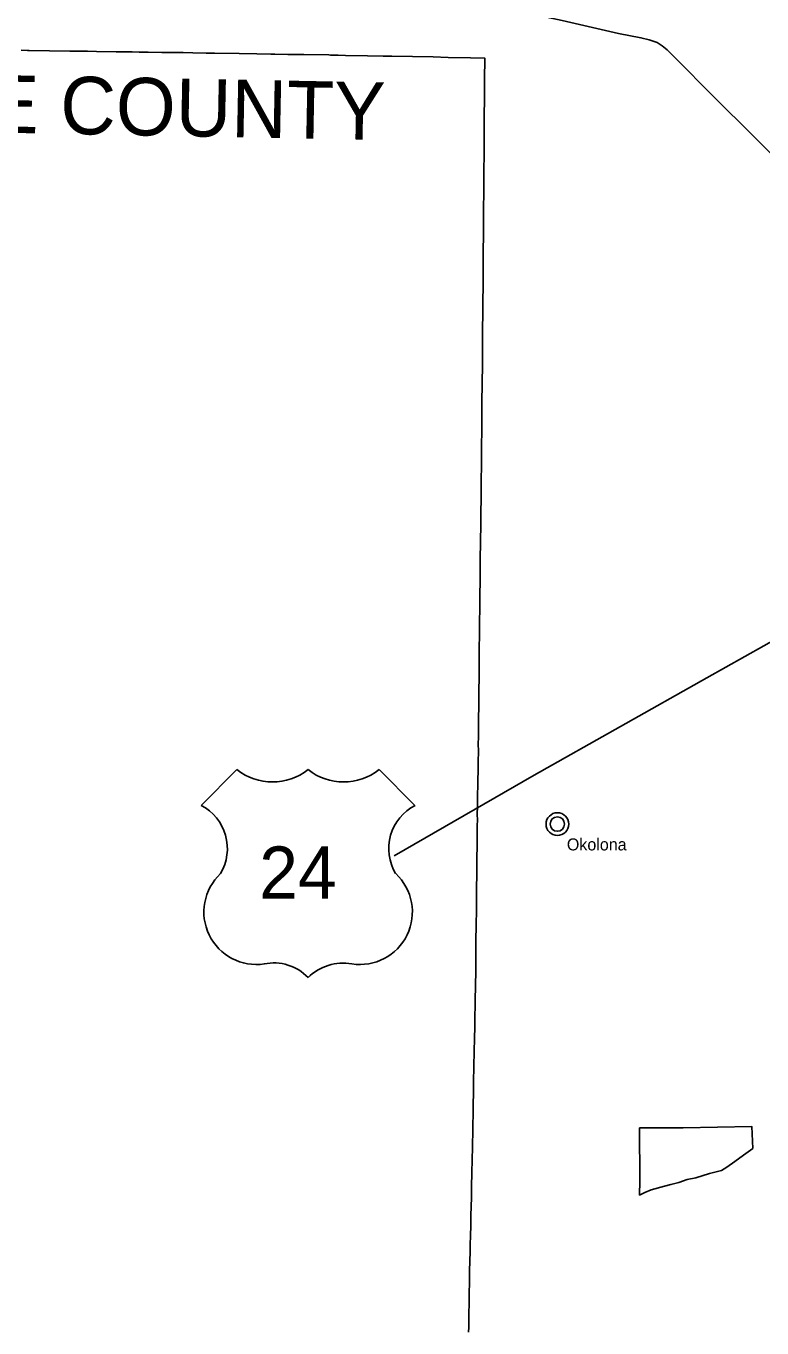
# Model space of a CAD drawing. Extents: x -62 to 810, y 0 to 440.
# Drawn here: x 166.9 to 239.8, y 199.3 to 328.2 of the extents above; entities that cross this region are included whole.
import ezdxf

# ---------------------------------------------------------------- set-up
doc = ezdxf.new("R2010")
doc.units = 0
for name, color, linetype in [('DV_X_Corp_Line', 7, 'Continuous'), ('GM_X_Adjacent_County_Text', 7, 'Continuous'), ('GM_X_Corporation_Text', 7, 'Continuous'), ('GM_X_County', 7, 'Continuous'), ('GM_X_State_Route', 7, 'Continuous'), ('PV_P_Text', 7, 'Continuous')]:
    doc.layers.add(name, color=color, linetype=linetype)

msp = doc.modelspace()

# ---------------------------------------------------------------- linework, layer by layer
at = {"layer": 'DV_X_Corp_Line'}
msp.add_lwpolyline([(227.72, 219.13), (232.04, 219.14), (238.83, 219.27), (238.92, 217.11), (238.02, 216.42), (237.15, 215.81), (236.36, 215.24), (235.84, 214.93), (234.64, 214.61), (233.27, 214.18), (232.41, 214.01), (231.6, 213.73), (230.81, 213.53), (230.18, 213.36), (228.86, 213), (228.24, 212.73), (227.71, 212.48), (227.73, 213.88)], close=True, dxfattribs=at)
for radius in [1.12, 0.71]:
    msp.add_circle((219.57, 249.22), radius, dxfattribs=at)
at = {"layer": 'GM_X_County'}
msp.add_lwpolyline([(166.45, 325.84), (167.1, 325.82), (167.25, 325.82), (171.27, 325.77), (172.55, 325.75), (173.04, 325.74), (173.92, 325.73), (175.87, 325.7), (177.45, 325.68), (178.15, 325.66), (178.52, 325.66), (179.03, 325.65), (180.41, 325.62), (181.44, 325.61), (181.83, 325.61), (182.01, 325.61), (182.52, 325.61), (183.48, 325.59), (184.8, 325.56), (185.6, 325.55), (188.06, 325.51), (189.79, 325.48), (191.2, 325.45), (191.58, 325.45), (192.86, 325.44), (193.78, 325.42), (193.89, 325.42), (194.45, 325.42), (196.93, 325.38), (197.1, 325.37), (197.25, 325.36), (197.86, 325.35), (198.6, 325.34), (200.77, 325.3), (202.31, 325.27), (203.19, 325.26), (207.26, 325.18), (208.77, 325.14), (210.98, 325.1), (212.37, 325.07), (212.37, 324.74), (212.36, 323.25), (212.35, 322.71), (212.34, 321.07), (212.33, 319.33), (212.33, 318.46), (212.33, 317.49), (212.33, 317.34), (212.32, 316.54), (212.31, 315.65), (212.29, 313.81), (212.29, 312.77), (212.28, 311.44), (212.27, 310.5), (212.26, 309.93), (212.26, 309.36), (212.25, 308.62), (212.24, 307.94), (212.24, 307.25), (212.23, 306.27), (212.22, 304.72), (212.22, 304.26), (212.22, 303.85), (212.21, 303.43), (212.21, 302.51), (212.21, 302.38), (212.21, 302.07), (212.2, 301.44), (212.19, 300.78), (212.18, 299.35), (212.17, 298.67), (212.17, 297.89), (212.16, 296.99), (212.16, 296.65), (212.15, 295.44), (212.14, 294.6), (212.14, 294.18), (212.13, 293.41), (212.11, 292.6), (212.11, 292.2), (212.1, 291.64), (212.1, 291.07), (212.09, 290.28), (212.08, 289.81), (212.08, 288.76), (212.08, 287.7), (212.07, 287.16), (212.06, 286.28), (212.04, 284.61), (212.03, 283.41), (212.01, 282.13), (212.01, 281.39), (211.99, 280.1), (211.99, 279.71), (211.98, 278.4), (211.97, 277.68), (211.96, 277.1), (211.94, 275.5), (211.91, 272.9), (211.9, 272.28), (211.88, 270.52), (211.88, 270.14), (211.87, 269.68), (211.86, 268.64), (211.85, 267.76), (211.83, 266.85), (211.82, 265.76), (211.81, 265.2), (211.81, 264.56), (211.81, 263.78), (211.8, 262.4), (211.78, 260.69), (211.77, 259.87), (211.76, 259.08), (211.75, 257.95), (211.74, 257.03), (211.74, 257), (211.75, 256.61), (211.72, 255.22), (211.72, 254.87), (211.71, 254.46), (211.7, 253.64), (211.69, 252.68), (211.67, 252.49), (211.66, 252.36), (211.66, 252.35), (211.65, 250.83), (211.64, 250.32), (211.65, 249.48), (211.64, 249.22), (211.64, 248.47), (211.62, 246.86), (211.61, 246.05), (211.6, 245.48), (211.6, 244.79), (211.59, 244.37), (211.57, 242.73), (211.56, 241.94), (211.56, 241.5), (211.55, 241.09), (211.55, 240.43), (211.54, 239.49), (211.51, 237.37), (211.49, 234.36), (211.47, 233.53), (211.47, 233.13), (211.44, 231.86), (211.43, 231.1), (211.41, 230.31), (211.38, 229.22), (211.36, 227.92), (211.33, 226.79), (211.33, 226.37), (211.31, 225.57), (211.29, 224.81), (211.28, 224.08), (211.27, 223.04), (211.26, 222.41), (211.24, 221.65), (211.23, 220.72), (211.2, 219.22), (211.19, 218.87), (211.12, 215.84), (211.1, 214.84), (211.07, 213.16), (211.05, 212.09), (211.03, 211.53), (211.01, 210.28), (210.99, 209.56), (210.96, 208.34), (210.94, 207.69), (210.92, 206.91), (210.89, 205.93), (210.89, 205.69), (210.88, 205.23), (210.88, 205), (210.86, 204.26), (210.86, 204.1), (210.86, 204), (210.84, 202.62), (210.82, 201.82), (210.81, 200.68), (210.8, 200.14), (210.79, 199.39), (210.78, 198.9)], dxfattribs=at)
at = {"layer": 'GM_X_State_Route'}
for points in [[(198.53, 333.88), (207.22, 331.68), (212.44, 330.67), (218.02, 329.23), (220.04, 328.78), (225.63, 327.52), (227.85, 327.08), (228.67, 326.87), (229.44, 326.61), (229.96, 326.29), (230.45, 325.9), (231.43, 324.88), (234.84, 321.46), (239.2, 317.13), (242.46, 313.89), (243.11, 313.25), (246.06, 310.2), (246.72, 309.53), (248.65, 307.6)], [(203.42, 246.07), (217.26, 254.07), (234.38, 263.69), (241.91, 267.93), (244.92, 269.63), (256.21, 275.94), (256.92, 276.34), (258.55, 277.28), (259.95, 278.2), (260.7, 278.72), (261.26, 279.12), (262.61, 280.12), (264.4, 281.53), (265.33, 282.35), (265.96, 282.89), (267.7, 284.59), (269.07, 285.92), (270.07, 286.92), (271.24, 288.1), (272.13, 288.96)]]:
    msp.add_lwpolyline(points, dxfattribs=at)
at = {"layer": 'PV_P_Text'}
for p, q in [((187.84, 254.61), (184.29, 251.07)), ((187.84, 254.61), (184.29, 251.07)), ((205.47, 251.07), (201.93, 254.61)), ((205.47, 251.07), (201.93, 254.61))]:
    msp.add_line(p, q, dxfattribs=at)
for centre, radius, start, end in [((191.36, 259.09), 5.7, 231.813, 308.187), ((191.36, 259.09), 5.7, 231.813, 308.187), ((198.4, 259.09), 5.7, 231.813, 308.187), ((198.4, 259.09), 5.7, 231.813, 308.187), ((182.07, 246.79), 4.82, 329.1175, 62.6108), ((182.07, 246.79), 4.82, 329.1175, 62.6108), ((207.69, 246.79), 4.82, 117.3892, 210.8825), ((207.69, 246.79), 4.82, 117.3892, 210.8825), ((189.76, 240.51), 5.2, 133.0046, 278.7282), ((189.76, 240.51), 5.2, 133.0046, 278.7282), ((200.01, 240.51), 5.2, 261.2718, 46.9954), ((200.01, 240.51), 5.2, 261.2718, 46.9954), ((191.5, 230.82), 4.65, 43.4177, 101.8742), ((191.5, 230.82), 4.65, 43.4177, 101.8742), ((198.36, 230.51), 4.94, 79.9613, 134.7468), ((198.36, 230.51), 4.94, 79.9613, 134.7468)]:
    msp.add_arc(centre, radius, start, end, dxfattribs=at)

# ---------------------------------------------------------------- texts
at = {"layer": 'GM_X_Adjacent_County_Text'}
msp.add_text('DEFIANCE COUNTY', height=5.7, rotation=358.9008, dxfattribs=at).set_placement((129.64, 318.35))
at = {"layer": 'GM_X_Corporation_Text'}
msp.add_text('Okolona', height=1.188, rotation=0, dxfattribs=at).set_placement((220.51, 246.61))
at = {"layer": 'PV_P_Text'}
msp.add_text('24', height=5.162, dxfattribs=at).set_placement((190.04, 241.84))

doc.saveas('drawing.dxf')
